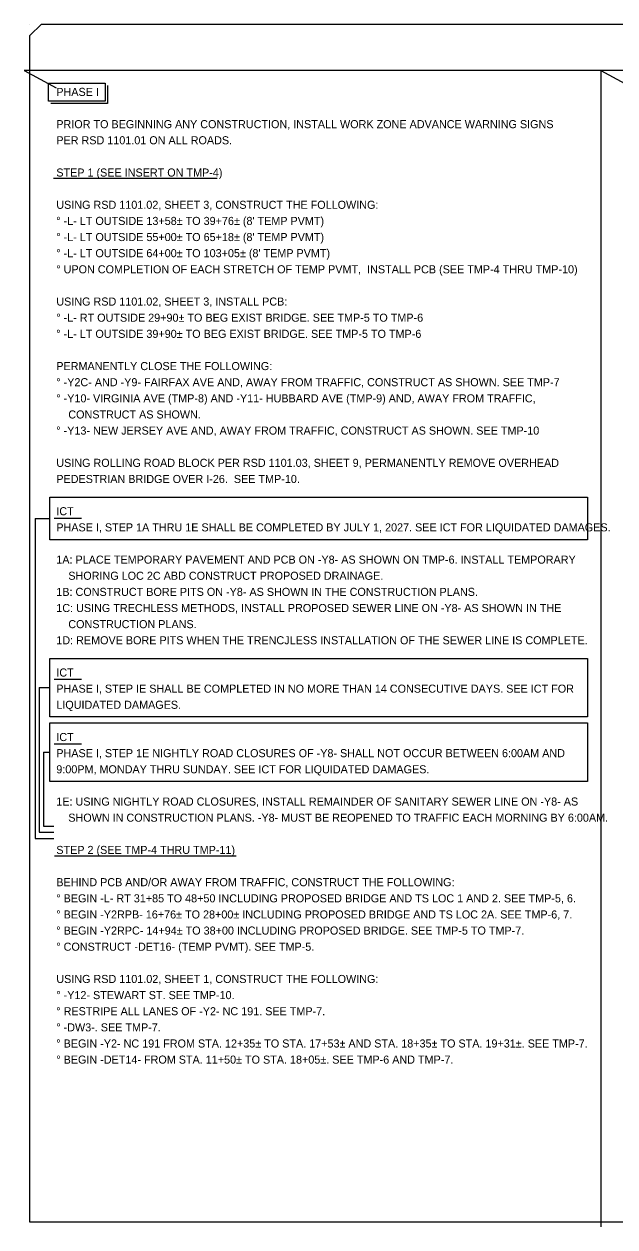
# Model space of a CAD drawing. Extents: x 2483905 to 2494512, y 366160 to 372330.
# Drawn here: x 2487012 to 2487524, y 370214 to 371258 of the extents above; entities that cross this region are included whole.
import ezdxf

# ---------------------------------------------------------------- set-up
doc = ezdxf.new("R2010")
doc.units = 0
for name, color, linetype in [('Scratch_Level_3', 7, 'Continuous'), ('Scratch_Level_6', 7, 'Continuous'), ('TC SHEET BORDER LINE THIN', 7, 'Continuous'), ('TC SHEET LAYOUT SHAPE', 7, 'Continuous')]:
    doc.layers.add(name, color=color, linetype=linetype)

msp = doc.modelspace()

# ---------------------------------------------------------------- linework, layer by layer
at = {"layer": 'Scratch_Level_3'}
msp.add_line((2487016.6, 371258.3), (2487016.6, 371258.3), dxfattribs=at)
at = {"layer": 'Scratch_Level_6'}
for p, q in [((2487011.6, 371218), (2487039.5, 371202.9)), ((2487511.6, 371218), (2487539.5, 371202.9))]:
    msp.add_line(p, q, dxfattribs=at)
at = {"layer": 'TC SHEET BORDER LINE THIN'}
for p, q in [((2488511.6, 371218), (2487011.6, 371218)), ((2487511.6, 371218), (2487511.6, 370214.2)), ((2487037.2, 371124.4), (2487037.2, 371124.4)), ((2487037.2, 371124.4), (2487179.1, 371124.4)), ((2487021.3, 370829.2), (2487033.9, 370829.2)), ((2487037.7, 370829.5), (2487061.3, 370829.5)), ((2487037.7, 370689.5), (2487061.3, 370689.5)), ((2487024.6, 370682.3), (2487033.9, 370682.3)), ((2487037.7, 370633.5), (2487061.3, 370633.5)), ((2487028.5, 370626.2), (2487033.9, 370626.2)), ((2487037.8, 370536.3), (2487037.8, 370536.3)), ((2487037.8, 370536.3), (2487195.6, 370536.3))]:
    msp.add_line(p, q, dxfattribs=at)
for points in [[(2487032.8, 371206.9), (2487081.8, 371206.9), (2487081.8, 371191.2), (2487032.8, 371191.2)], [(2487033.9, 370847.7), (2487500.2, 370847.7), (2487500.2, 370810.7), (2487033.9, 370810.7)], [(2487033.9, 370707.7), (2487500.2, 370707.7), (2487500.2, 370657), (2487033.9, 370657)], [(2487033.9, 370651.7), (2487500.2, 370651.7), (2487500.2, 370600.7), (2487033.9, 370600.7)]]:
    msp.add_lwpolyline(points, close=True, dxfattribs=at)
for points in [[(2487083.8, 371204.9), (2487083.8, 371189.2), (2487034.8, 371189.2)], [(2487021.3, 370829.2), (2487021.3, 370551.4), (2487037.4, 370551.4)], [(2487024.6, 370682.3), (2487024.6, 370556.8), (2487037.4, 370556.8)], [(2487028.5, 370626.2), (2487028.5, 370561.9), (2487037.4, 370561.9)]]:
    msp.add_lwpolyline(points, dxfattribs=at)
at = {"layer": 'TC SHEET LAYOUT SHAPE'}
msp.add_lwpolyline([(2487016.6, 370666.8), (2487016.6, 370976.2), (2487016.6, 371248.3), (2487026.6, 371258.3), (2487469.6, 371258.3), (2487940.6, 371258.3), (2488261.6, 371258.3), (2488261.6, 371178.3), (2488346.6, 371178.3), (2488346.6, 371226.3), (2488506.6, 371226.3), (2488506.6, 370891.3), (2488506.6, 370612.1), (2488506.6, 370360.8), (2487778.4, 370360.8), (2487778.4, 370218.3), (2487608.9, 370218.3), (2487256.1, 370218.3), (2487016.6, 370218.3)], close=True, dxfattribs=at)

# ---------------------------------------------------------------- texts
at = {"layer": 'TC SHEET BORDER LINE THIN'}
for s, p in [('PHASE I', (2487039.5, 371195.9)), ('PRIOR TO BEGINNING ANY CONSTRUCTION, INSTALL WORK ZONE ADVANCE WARNING SIGNS', (2487039.5, 371167.9)), ('PER RSD 1101.01 ON ALL ROADS.', (2487039.5, 371153.9)), ('STEP 1 (SEE INSERT ON TMP-4)', (2487039.5, 371125.9)), ('USING RSD 1101.02, SHEET 3, CONSTRUCT THE FOLLOWING:', (2487039.5, 371097.9)), ("° -L- LT OUTSIDE 13+58± TO 39+76± (8' TEMP PVMT)", (2487039.5, 371083.9)), ("° -L- LT OUTSIDE 55+00± TO 65+18± (8' TEMP PVMT)", (2487039.5, 371069.9)), ("° -L- LT OUTSIDE 64+00± TO 103+05± (8' TEMP PVMT)", (2487039.5, 371055.9)), ('° UPON COMPLETION OF EACH STRETCH OF TEMP PVMT,  INSTALL PCB (SEE TMP-4 THRU TMP-10)', (2487039.5, 371041.9)), ('USING RSD 1101.02, SHEET 3, INSTALL PCB:', (2487039.5, 371013.9)), ('° -L- RT OUTSIDE 29+90± TO BEG EXIST BRIDGE. SEE TMP-5 TO TMP-6', (2487039.5, 370999.9)), ('° -L- LT OUTSIDE 39+90± TO BEG EXIST BRIDGE. SEE TMP-5 TO TMP-6', (2487039.5, 370985.9)), ('PERMANENTLY CLOSE THE FOLLOWING:', (2487039.5, 370957.9)), ('° -Y2C- AND -Y9- FAIRFAX AVE AND, AWAY FROM TRAFFIC, CONSTRUCT AS SHOWN. SEE TMP-7', (2487039.5, 370943.9)), ('° -Y10- VIRGINIA AVE (TMP-8) AND -Y11- HUBBARD AVE (TMP-9) AND, AWAY FROM TRAFFIC,', (2487039.5, 370929.9)), ('    CONSTRUCT AS SHOWN.', (2487039.5, 370915.9)), ('° -Y13- NEW JERSEY AVE AND, AWAY FROM TRAFFIC, CONSTRUCT AS SHOWN. SEE TMP-10', (2487039.5, 370901.9)), ('USING ROLLING ROAD BLOCK PER RSD 1101.03, SHEET 9, PERMANENTLY REMOVE OVERHEAD ', (2487039.5, 370873.9)), ('PEDESTRIAN BRIDGE OVER I-26.  SEE TMP-10.', (2487039.5, 370859.9)), ('ICT', (2487039.5, 370831.9)), ('PHASE I, STEP 1A THRU 1E SHALL BE COMPLETED BY JULY 1, 2027. SEE ICT FOR LIQUIDATED DAMAGES.', (2487039.5, 370817.9)), ('1A: PLACE TEMPORARY PAVEMENT AND PCB ON -Y8- AS SHOWN ON TMP-6. INSTALL TEMPORARY ', (2487039.5, 370789.9)), ('    SHORING LOC 2C ABD CONSTRUCT PROPOSED DRAINAGE.', (2487039.5, 370775.9)), ('1B: CONSTRUCT BORE PITS ON -Y8- AS SHOWN IN THE CONSTRUCTION PLANS.', (2487039.5, 370761.9)), ('1C: USING TRECHLESS METHODS, INSTALL PROPOSED SEWER LINE ON -Y8- AS SHOWN IN THE ', (2487039.5, 370747.9)), ('    CONSTRUCTION PLANS.', (2487039.5, 370733.9)), ('1D: REMOVE BORE PITS WHEN THE TRENCJLESS INSTALLATION OF THE SEWER LINE IS COMPLETE.', (2487039.5, 370719.9)), ('ICT', (2487039.5, 370691.9)), ('PHASE I, STEP IE SHALL BE COMPLETED IN NO MORE THAN 14 CONSECUTIVE DAYS. SEE ICT FOR ', (2487039.5, 370677.9)), ('LIQUIDATED DAMAGES.', (2487039.5, 370663.9)), ('ICT', (2487039.5, 370635.9)), ('PHASE I, STEP 1E NIGHTLY ROAD CLOSURES OF -Y8- SHALL NOT OCCUR BETWEEN 6:00AM AND ', (2487039.5, 370621.9)), ('9:00PM, MONDAY THRU SUNDAY. SEE ICT FOR LIQUIDATED DAMAGES.', (2487039.5, 370607.9)), ('1E: USING NIGHTLY ROAD CLOSURES, INSTALL REMAINDER OF SANITARY SEWER LINE ON -Y8- AS ', (2487039.5, 370579.9)), ('    SHOWN IN CONSTRUCTION PLANS. -Y8- MUST BE REOPENED TO TRAFFIC EACH MORNING BY 6:00AM.', (2487039.5, 370565.9)), ('STEP 2 (SEE TMP-4 THRU TMP-11)', (2487039.5, 370537.9)), ('BEHIND PCB AND/OR AWAY FROM TRAFFIC, CONSTRUCT THE FOLLOWING:', (2487039.5, 370509.9)), ('° BEGIN -L- RT 31+85 TO 48+50 INCLUDING PROPOSED BRIDGE AND TS LOC 1 AND 2. SEE TMP-5, 6.', (2487039.5, 370495.9)), ('° BEGIN -Y2RPB- 16+76± TO 28+00± INCLUDING PROPOSED BRIDGE AND TS LOC 2A. SEE TMP-6, 7.', (2487039.5, 370481.9)), ('° BEGIN -Y2RPC- 14+94± TO 38+00 INCLUDING PROPOSED BRIDGE. SEE TMP-5 TO TMP-7.', (2487039.5, 370467.9)), ('° CONSTRUCT -DET16- (TEMP PVMT). SEE TMP-5.', (2487039.5, 370453.9)), ('USING RSD 1101.02, SHEET 1, CONSTRUCT THE FOLLOWING:', (2487039.5, 370425.9)), ('° -Y12- STEWART ST. SEE TMP-10.', (2487039.5, 370411.9)), ('° RESTRIPE ALL LANES OF -Y2- NC 191. SEE TMP-7.', (2487039.5, 370397.9)), ('° -DW3-. SEE TMP-7.', (2487039.5, 370383.9)), ('° BEGIN -Y2- NC 191 FROM STA. 12+35± TO STA. 17+53± AND STA. 18+35± TO STA. 19+31±. SEE TMP-7.', (2487039.5, 370369.9)), ('° BEGIN -DET14- FROM STA. 11+50± TO STA. 18+05±. SEE TMP-6 AND TMP-7.', (2487039.5, 370355.9))]:
    msp.add_text(s, height=7, dxfattribs=at).set_placement(p)

doc.saveas('drawing.dxf')
